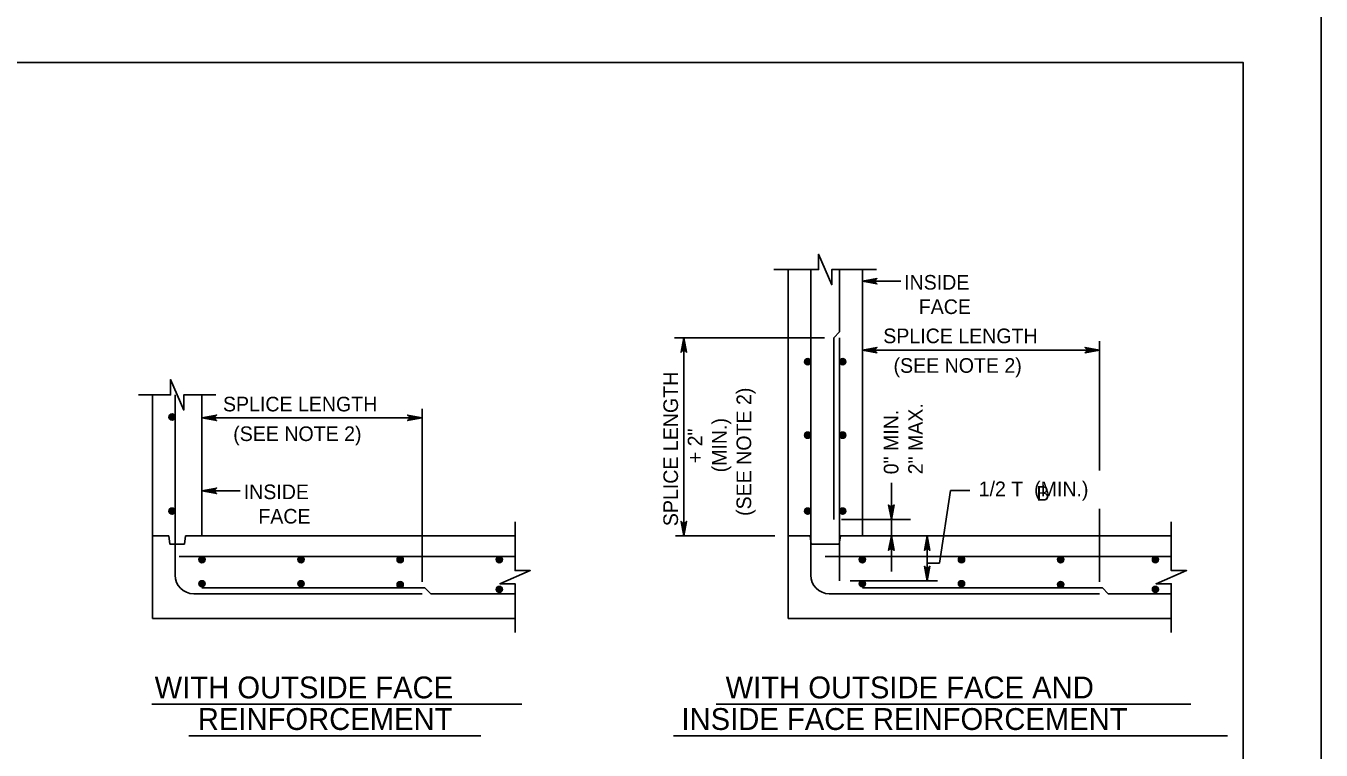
# Model space of a CAD drawing. Extents: x -6420 to 49575, y -4552 to 11624.
# Drawn here: x 3745 to 4616, y 7215 to 7702 of the extents above; entities that cross this region are included whole.
import ezdxf

# ---------------------------------------------------------------- set-up
doc = ezdxf.new("R2010")
doc.units = 0
doc.layers.add('1', color=7, linetype='Continuous')
doc.layers.add('PLT-BNDY', color=7, linetype='Continuous')

msp = doc.modelspace()

# ---------------------------------------------------------------- linework, layer by layer
at = {"layer": '1'}
for p, q in [((4257.79, 7303.09), (4257.79, 7537.79)), ((4273.09, 7332.26), (4273.09, 7537.79)), ((4292.49, 7495.98), (4292.49, 7537.79)), ((4307.79, 7537.79), (4307.79, 7358.65)), ((4307.79, 7529.92), (4333.56, 7529.92)), ((4292.49, 7495.98), (4288.49, 7491.98)), ((4181.37, 7491.98), (4282.24, 7491.98)), ((4187.65, 7491.98), (4187.65, 7358.65)), ((4288.49, 7369.76), (4288.49, 7491.98)), ((4292.49, 7328.51), (4292.49, 7491.98)), ((4467.38, 7489.73), (4467.38, 7402.75)), ((4307.79, 7483.63), (4467.38, 7483.63)), ((3830.2, 7303.09), (3830.2, 7453.51)), ((3845.48, 7332.26), (3845.48, 7453.51)), ((3863.53, 7453.51), (3863.53, 7358.65)), ((4011.69, 7444.18), (4011.69, 7327.74)), ((3863.53, 7438.09), (4011.69, 7438.09)), ((3863.53, 7389), (3889.3, 7389)), ((4327.28, 7334.61), (4327.28, 7394.25)), ((4367.02, 7389.18), (4359.63, 7340.25)), ((4367.02, 7389.18), (4380.11, 7389.18)), ((4467.38, 7376.76), (4467.38, 7327.74)), ((4293.74, 7369.76), (4340.2, 7369.76)), ((3830.18, 7358.65), (3841.31, 7358.65)), ((3842, 7353.1), (3841.31, 7358.65)), ((3851.72, 7353.1), (3852.41, 7358.65)), ((3852.41, 7358.65), (3863.53, 7358.65)), ((3863.53, 7358.65), (4074.18, 7358.65)), ((4181.99, 7358.65), (4248.82, 7358.65)), ((4257.79, 7358.65), (4272.61, 7358.65)), ((4273.3, 7353.1), (4272.61, 7358.65)), ((4292.28, 7353.1), (4292.98, 7358.65)), ((4292.98, 7358.65), (4307.79, 7358.65)), ((4307.79, 7358.65), (4515.61, 7358.65)), ((4351.32, 7358.65), (4351.32, 7328.51)), ((3842, 7353.1), (3851.72, 7353.1)), ((4273.3, 7353.1), (4292.28, 7353.1)), ((3848.25, 7344.76), (4074.18, 7344.76)), ((4282.79, 7344.76), (4515.61, 7344.76)), ((4351.32, 7340.25), (4359.63, 7340.25)), ((4299.51, 7328.51), (4358.23, 7328.51)), ((4011.69, 7319.76), (3857.98, 7319.76)), ((4013.53, 7323.76), (3863.53, 7323.76)), ((4013.53, 7323.76), (4017.53, 7319.76)), ((4074.18, 7319.76), (4017.53, 7319.76)), ((4467.38, 7319.76), (4285.57, 7319.76)), ((4469.22, 7323.76), (4307.79, 7323.76)), ((4469.22, 7323.76), (4473.22, 7319.76)), ((4515.61, 7319.76), (4473.22, 7319.76)), ((4074.18, 7303.09), (3830.2, 7303.09)), ((4515.61, 7303.09), (4257.79, 7303.09)), ((3829.77, 7245.44), (4078.64, 7245.44)), ((4209.48, 7245.44), (4528.86, 7245.44)), ((3854.61, 7224.24), (4051.15, 7224.24)), ((4180.81, 7224.24), (4553.42, 7224.24))]:
    msp.add_line(p, q, dxfattribs=at)
for points in [[(4563.89, 5826.65), (4563.89, 7677.05), (1985.15, 7677.05), (1985.15, 5826.65), (4563.89, 5826.65), (4563.89, 5913.13), (3907.72, 5913.13), (3907.72, 6125.33), (4563.89, 6125.33), (4563.89, 6220.35), (3907.72, 6220.35), (3907.72, 5826.65), (4166.25, 5826.65), (4166.25, 5913.13), (4166.25, 5826.65), (4418.88, 5826.65), (4418.88, 5913.13), (4418.88, 5872.72), (4563.89, 5872.72)], [(4248.34, 7537.79), (4278.38, 7537.79), (4278.38, 7548.03), (4287.2, 7527.56), (4287.2, 7537.79), (4317.24, 7537.79)], [(4307.79, 7529.92), (4317.58, 7531.76), (4317.2, 7531.5), (4316.82, 7531.24), (4316.63, 7530.91), (4316.43, 7530.58), (4316.38, 7530.25), (4316.32, 7529.92), (4316.38, 7529.59), (4316.43, 7529.27), (4316.63, 7528.94), (4316.82, 7528.61), (4317.2, 7528.35), (4317.58, 7528.09), (4307.79, 7529.92), (4317.2, 7528.35), (4316.82, 7528.61), (4307.79, 7529.92), (4316.63, 7528.94), (4316.43, 7529.27), (4307.79, 7529.92), (4316.38, 7529.59), (4316.32, 7529.92), (4307.79, 7529.92), (4316.38, 7530.25), (4316.43, 7530.58), (4307.79, 7529.92), (4316.63, 7530.91), (4316.82, 7531.24), (4307.79, 7529.92), (4317.2, 7531.5)], [(4187.65, 7491.98), (4189.49, 7482.2), (4189.22, 7482.57), (4188.96, 7482.95), (4188.63, 7483.15), (4188.31, 7483.34), (4187.98, 7483.4), (4187.65, 7483.45), (4187.32, 7483.4), (4186.99, 7483.34), (4186.67, 7483.15), (4186.34, 7482.95), (4186.08, 7482.57), (4185.82, 7482.2), (4187.65, 7491.98), (4186.08, 7482.57), (4186.34, 7482.95), (4187.65, 7491.98), (4186.67, 7483.15), (4186.99, 7483.34), (4187.65, 7491.98), (4187.32, 7483.4), (4187.65, 7483.45), (4187.65, 7491.98), (4187.98, 7483.4), (4188.31, 7483.34), (4187.65, 7491.98), (4188.63, 7483.15), (4188.96, 7482.95), (4187.65, 7491.98), (4189.22, 7482.57)], [(4307.79, 7483.63), (4317.58, 7485.46), (4317.2, 7485.2), (4316.82, 7484.94), (4316.63, 7484.61), (4316.43, 7484.29), (4316.38, 7483.96), (4316.32, 7483.63), (4316.38, 7483.3), (4316.43, 7482.97), (4316.63, 7482.64), (4316.82, 7482.32), (4317.2, 7482.06), (4317.58, 7481.79), (4307.79, 7483.63), (4317.2, 7482.06), (4316.82, 7482.32), (4307.79, 7483.63), (4316.63, 7482.64), (4316.43, 7482.97), (4307.79, 7483.63), (4316.38, 7483.3), (4316.32, 7483.63), (4307.79, 7483.63), (4316.38, 7483.96), (4316.43, 7484.29), (4307.79, 7483.63), (4316.63, 7484.61), (4316.82, 7484.94), (4307.79, 7483.63), (4317.2, 7485.2)], [(4467.38, 7483.63), (4457.59, 7481.79), (4457.97, 7482.06), (4458.35, 7482.32), (4458.54, 7482.64), (4458.74, 7482.97), (4458.79, 7483.3), (4458.85, 7483.63), (4458.79, 7483.96), (4458.74, 7484.29), (4458.54, 7484.61), (4458.35, 7484.94), (4457.97, 7485.2), (4457.59, 7485.46), (4467.38, 7483.63), (4457.97, 7485.2), (4458.35, 7484.94), (4467.38, 7483.63), (4458.54, 7484.61), (4458.74, 7484.29), (4467.38, 7483.63), (4458.79, 7483.96), (4458.85, 7483.63), (4467.38, 7483.63), (4458.79, 7483.3), (4458.74, 7482.97), (4467.38, 7483.63), (4458.54, 7482.64), (4458.35, 7482.32), (4467.38, 7483.63), (4457.97, 7482.06)], [(3872.98, 7453.51), (3851.28, 7453.51), (3851.28, 7443.28), (3842.46, 7463.75), (3842.46, 7453.51), (3820.75, 7453.51)], [(3863.53, 7438.09), (3873.32, 7439.93), (3872.94, 7439.67), (3872.57, 7439.41), (3872.37, 7439.08), (3872.18, 7438.75), (3872.12, 7438.42), (3872.06, 7438.09), (3872.12, 7437.77), (3872.18, 7437.44), (3872.37, 7437.11), (3872.57, 7436.78), (3872.94, 7436.52), (3873.32, 7436.26), (3863.53, 7438.09), (3872.94, 7436.52), (3872.57, 7436.78), (3863.53, 7438.09), (3872.37, 7437.11), (3872.18, 7437.44), (3863.53, 7438.09), (3872.12, 7437.77), (3872.06, 7438.09), (3863.53, 7438.09), (3872.12, 7438.42), (3872.18, 7438.75), (3863.53, 7438.09), (3872.37, 7439.08), (3872.57, 7439.41), (3863.53, 7438.09), (3872.94, 7439.67)], [(4011.69, 7438.09), (4001.91, 7436.26), (4002.28, 7436.52), (4002.66, 7436.78), (4002.86, 7437.11), (4003.05, 7437.44), (4003.11, 7437.77), (4003.16, 7438.09), (4003.11, 7438.42), (4003.05, 7438.75), (4002.86, 7439.08), (4002.66, 7439.41), (4002.28, 7439.67), (4001.91, 7439.93), (4011.69, 7438.09), (4002.28, 7439.67), (4002.66, 7439.41), (4011.69, 7438.09), (4002.86, 7439.08), (4003.05, 7438.75), (4011.69, 7438.09), (4003.11, 7438.42), (4003.16, 7438.09), (4011.69, 7438.09), (4003.11, 7437.77), (4003.05, 7437.44), (4011.69, 7438.09), (4002.86, 7437.11), (4002.66, 7436.78), (4011.69, 7438.09), (4002.28, 7436.52)], [(3863.53, 7389), (3873.32, 7390.84), (3872.94, 7390.57), (3872.57, 7390.31), (3872.37, 7389.99), (3872.18, 7389.66), (3872.12, 7389.33), (3872.06, 7389), (3872.12, 7388.67), (3872.18, 7388.34), (3872.37, 7388.02), (3872.57, 7387.69), (3872.94, 7387.43), (3873.32, 7387.17), (3863.53, 7389), (3872.94, 7387.43), (3872.57, 7387.69), (3863.53, 7389), (3872.37, 7388.02), (3872.18, 7388.34), (3863.53, 7389), (3872.12, 7388.67), (3872.06, 7389), (3863.53, 7389), (3872.12, 7389.33), (3872.18, 7389.66), (3863.53, 7389), (3872.37, 7389.99), (3872.57, 7390.31), (3863.53, 7389), (3872.94, 7390.57)], [(4327.28, 7369.76), (4325.44, 7379.55), (4325.71, 7379.17), (4325.97, 7378.79), (4326.29, 7378.6), (4326.62, 7378.41), (4326.95, 7378.35), (4327.28, 7378.29), (4327.61, 7378.35), (4327.94, 7378.41), (4328.26, 7378.6), (4328.59, 7378.79), (4328.85, 7379.17), (4329.11, 7379.55), (4327.28, 7369.76), (4328.85, 7379.17), (4328.59, 7378.79), (4327.28, 7369.76), (4328.26, 7378.6), (4327.94, 7378.41), (4327.28, 7369.76), (4327.61, 7378.35), (4327.28, 7378.29), (4327.28, 7369.76), (4326.95, 7378.35), (4326.62, 7378.41), (4327.28, 7369.76), (4326.29, 7378.6), (4325.97, 7378.79), (4327.28, 7369.76), (4325.71, 7379.17)], [(4074.18, 7368.1), (4074.18, 7335.28), (4084.42, 7335.28), (4063.94, 7326.46), (4074.18, 7326.46), (4074.18, 7293.64)], [(4187.65, 7358.65), (4185.82, 7368.43), (4186.08, 7368.06), (4186.34, 7367.68), (4186.67, 7367.49), (4186.99, 7367.29), (4187.32, 7367.24), (4187.65, 7367.18), (4187.98, 7367.24), (4188.31, 7367.29), (4188.63, 7367.49), (4188.96, 7367.68), (4189.22, 7368.06), (4189.49, 7368.43), (4187.65, 7358.65), (4189.22, 7368.06), (4188.96, 7367.68), (4187.65, 7358.65), (4188.63, 7367.49), (4188.31, 7367.29), (4187.65, 7358.65), (4187.98, 7367.24), (4187.65, 7367.18), (4187.65, 7358.65), (4187.32, 7367.24), (4186.99, 7367.29), (4187.65, 7358.65), (4186.67, 7367.49), (4186.34, 7367.68), (4187.65, 7358.65), (4186.08, 7368.06)], [(4515.61, 7368.1), (4515.61, 7335.28), (4525.85, 7335.28), (4505.37, 7326.46), (4515.61, 7326.46), (4515.61, 7293.64)], [(4327.28, 7358.65), (4329.11, 7348.86), (4328.85, 7349.24), (4328.59, 7349.62), (4328.26, 7349.81), (4327.94, 7350.01), (4327.61, 7350.06), (4327.28, 7350.12), (4326.95, 7350.06), (4326.62, 7350.01), (4326.29, 7349.81), (4325.97, 7349.62), (4325.71, 7349.24), (4325.44, 7348.86), (4327.28, 7358.65), (4325.71, 7349.24), (4325.97, 7349.62), (4327.28, 7358.65), (4326.29, 7349.81), (4326.62, 7350.01), (4327.28, 7358.65), (4326.95, 7350.06), (4327.28, 7350.12), (4327.28, 7358.65), (4327.61, 7350.06), (4327.94, 7350.01), (4327.28, 7358.65), (4328.26, 7349.81), (4328.59, 7349.62), (4327.28, 7358.65), (4328.85, 7349.24)], [(4351.32, 7358.65), (4353.16, 7348.86), (4352.9, 7349.24), (4352.64, 7349.62), (4352.31, 7349.81), (4351.98, 7350.01), (4351.65, 7350.06), (4351.32, 7350.12), (4350.99, 7350.06), (4350.67, 7350.01), (4350.34, 7349.81), (4350.01, 7349.62), (4349.75, 7349.24), (4349.49, 7348.86), (4351.32, 7358.65), (4349.75, 7349.24), (4350.01, 7349.62), (4351.32, 7358.65), (4350.34, 7349.81), (4350.67, 7350.01), (4351.32, 7358.65), (4350.99, 7350.06), (4351.32, 7350.12), (4351.32, 7358.65), (4351.65, 7350.06), (4351.98, 7350.01), (4351.32, 7358.65), (4352.31, 7349.81), (4352.64, 7349.62), (4351.32, 7358.65), (4352.9, 7349.24)], [(4351.32, 7328.51), (4349.49, 7338.29), (4349.75, 7337.92), (4350.01, 7337.54), (4350.34, 7337.34), (4350.67, 7337.15), (4350.99, 7337.09), (4351.32, 7337.04), (4351.65, 7337.09), (4351.98, 7337.15), (4352.31, 7337.34), (4352.64, 7337.54), (4352.9, 7337.92), (4353.16, 7338.29), (4351.32, 7328.51), (4352.9, 7337.92), (4352.64, 7337.54), (4351.32, 7328.51), (4352.31, 7337.34), (4351.98, 7337.15), (4351.32, 7328.51), (4351.65, 7337.09), (4351.32, 7337.04), (4351.32, 7328.51), (4350.99, 7337.09), (4350.67, 7337.15), (4351.32, 7328.51), (4350.34, 7337.34), (4350.01, 7337.54), (4351.32, 7328.51), (4349.75, 7337.92)]]:
    msp.add_lwpolyline(points, dxfattribs=at)
for centre, radius in [((4271, 7475.83), 2.08), ((4271, 7475.83), 1.94), ((4271, 7475.83), 1.79), ((4271, 7475.83), 1.64), ((4271, 7475.83), 1.49), ((4271, 7475.83), 1.34), ((4271, 7475.83), 1.2), ((4271, 7475.83), 1.05), ((4271, 7475.83), 0.9), ((4271, 7475.83), 0.752), ((4271, 7475.83), 0.604), ((4271, 7475.83), 0.456), ((4271, 7475.83), 0.308), ((4271, 7475.83), 0.16), ((4294.58, 7475.83), 2.08), ((4294.58, 7475.83), 1.94), ((4294.58, 7475.83), 1.79), ((4294.58, 7475.83), 1.64), ((4294.58, 7475.83), 1.49), ((4294.58, 7475.83), 1.34), ((4294.58, 7475.83), 1.2), ((4294.58, 7475.83), 1.05), ((4294.58, 7475.83), 0.9), ((4294.58, 7475.83), 0.752), ((4294.58, 7475.83), 0.604), ((4294.58, 7475.83), 0.456), ((4294.58, 7475.83), 0.308), ((4294.58, 7475.83), 0.16), ((3843.4, 7438.61), 2.08), ((3843.4, 7438.61), 1.94), ((3843.4, 7438.61), 1.79), ((3843.4, 7438.61), 1.64), ((3843.4, 7438.61), 1.49), ((3843.4, 7438.61), 1.34), ((3843.4, 7438.61), 1.2), ((3843.4, 7438.61), 1.05), ((3843.4, 7438.61), 0.9), ((3843.4, 7438.61), 0.752), ((3843.4, 7438.61), 0.604), ((3843.4, 7438.61), 0.456), ((3843.4, 7438.61), 0.308), ((3843.4, 7438.61), 0.16), ((4271, 7426.41), 2.08), ((4271, 7426.41), 1.94), ((4271, 7426.41), 1.79), ((4271, 7426.41), 1.64), ((4271, 7426.41), 1.49), ((4271, 7426.41), 1.34), ((4271, 7426.41), 1.2), ((4271, 7426.41), 1.05), ((4271, 7426.41), 0.9), ((4271, 7426.41), 0.752), ((4271, 7426.41), 0.604), ((4271, 7426.41), 0.456), ((4271, 7426.41), 0.308), ((4271, 7426.41), 0.16), ((4294.58, 7426.41), 2.08), ((4294.58, 7426.41), 1.94), ((4294.58, 7426.41), 1.79), ((4294.58, 7426.41), 1.64), ((4294.58, 7426.41), 1.49), ((4294.58, 7426.41), 1.34), ((4294.58, 7426.41), 1.2), ((4294.58, 7426.41), 1.05), ((4294.58, 7426.41), 0.9), ((4294.58, 7426.41), 0.752), ((4294.58, 7426.41), 0.604), ((4294.58, 7426.41), 0.456), ((4294.58, 7426.41), 0.308), ((4294.58, 7426.41), 0.16), ((3843.4, 7375.32), 2.08), ((3843.4, 7375.32), 1.94), ((3843.4, 7375.32), 1.79), ((3843.4, 7375.32), 1.64), ((3843.4, 7375.32), 1.49), ((3843.4, 7375.32), 1.34), ((3843.4, 7375.32), 1.2), ((3843.4, 7375.32), 1.05), ((3843.4, 7375.32), 0.9), ((3843.4, 7375.32), 0.752), ((3843.4, 7375.32), 0.604), ((3843.4, 7375.32), 0.456), ((3843.4, 7375.32), 0.308), ((3843.4, 7375.32), 0.16), ((4271, 7375.32), 2.08), ((4271, 7375.32), 1.94), ((4271, 7375.32), 1.79), ((4271, 7375.32), 1.64), ((4271, 7375.32), 1.49), ((4271, 7375.32), 1.34), ((4271, 7375.32), 1.2), ((4271, 7375.32), 1.05), ((4271, 7375.32), 0.9), ((4271, 7375.32), 0.752), ((4271, 7375.32), 0.604), ((4271, 7375.32), 0.456), ((4271, 7375.32), 0.308), ((4271, 7375.32), 0.16), ((4294.58, 7375.32), 2.08), ((4294.58, 7375.32), 1.94), ((4294.58, 7375.32), 1.79), ((4294.58, 7375.32), 1.64), ((4294.58, 7375.32), 1.49), ((4294.58, 7375.32), 1.34), ((4294.58, 7375.32), 1.2), ((4294.58, 7375.32), 1.05), ((4294.58, 7375.32), 0.9), ((4294.58, 7375.32), 0.752), ((4294.58, 7375.32), 0.604), ((4294.58, 7375.32), 0.456), ((4294.58, 7375.32), 0.308), ((4294.58, 7375.32), 0.16), ((3863.53, 7342.68), 2.08), ((3863.53, 7342.68), 1.94), ((3863.53, 7342.68), 1.79), ((3863.53, 7342.68), 1.64), ((3863.53, 7342.68), 1.49), ((3863.53, 7342.68), 1.34), ((3863.53, 7342.68), 1.2), ((3863.53, 7342.68), 1.05), ((3863.53, 7342.68), 0.9), ((3863.53, 7342.68), 0.752), ((3863.53, 7342.68), 0.604), ((3863.53, 7342.68), 0.456), ((3863.53, 7342.68), 0.308), ((3863.53, 7342.68), 0.16), ((3930.2, 7342.68), 2.08), ((3930.2, 7342.68), 1.94), ((3930.2, 7342.68), 1.79), ((3930.2, 7342.68), 1.64), ((3930.2, 7342.68), 1.49), ((3930.2, 7342.68), 1.34), ((3930.2, 7342.68), 1.2), ((3930.2, 7342.68), 1.05), ((3930.2, 7342.68), 0.9), ((3930.2, 7342.68), 0.752), ((3930.2, 7342.68), 0.604), ((3930.2, 7342.68), 0.456), ((3930.2, 7342.68), 0.308), ((3930.2, 7342.68), 0.16), ((3996.87, 7342.68), 2.08), ((3996.87, 7342.68), 1.94), ((3996.87, 7342.68), 1.79), ((3996.87, 7342.68), 1.64), ((3996.87, 7342.68), 1.49), ((3996.87, 7342.68), 1.34), ((3996.87, 7342.68), 1.2), ((3996.87, 7342.68), 1.05), ((3996.87, 7342.68), 0.9), ((3996.87, 7342.68), 0.752), ((3996.87, 7342.68), 0.604), ((3996.87, 7342.68), 0.456), ((3996.87, 7342.68), 0.308), ((3996.87, 7342.68), 0.16), ((4063.53, 7342.68), 2.08), ((4063.53, 7342.68), 1.94), ((4063.53, 7342.68), 1.79), ((4063.53, 7342.68), 1.64), ((4063.53, 7342.68), 1.49), ((4063.53, 7342.68), 1.34), ((4063.53, 7342.68), 1.2), ((4063.53, 7342.68), 1.05), ((4063.53, 7342.68), 0.9), ((4063.53, 7342.68), 0.752), ((4063.53, 7342.68), 0.604), ((4063.53, 7342.68), 0.456), ((4063.53, 7342.68), 0.308), ((4063.53, 7342.68), 0.16), ((4307.8, 7342.68), 2.08), ((4307.8, 7342.68), 1.94), ((4307.8, 7342.68), 1.79), ((4307.8, 7342.68), 1.64), ((4307.8, 7342.68), 1.49), ((4307.8, 7342.68), 1.34), ((4307.8, 7342.68), 1.2), ((4307.8, 7342.68), 1.05), ((4307.8, 7342.68), 0.9), ((4307.8, 7342.68), 0.752), ((4307.8, 7342.68), 0.604), ((4307.8, 7342.68), 0.456), ((4307.8, 7342.68), 0.308), ((4307.8, 7342.68), 0.16), ((4374.47, 7342.68), 2.08), ((4374.47, 7342.68), 1.94), ((4374.47, 7342.68), 1.79), ((4374.47, 7342.68), 1.64), ((4374.47, 7342.68), 1.49), ((4374.47, 7342.68), 1.34), ((4374.47, 7342.68), 1.2), ((4374.47, 7342.68), 1.05), ((4374.47, 7342.68), 0.9), ((4374.47, 7342.68), 0.752), ((4374.47, 7342.68), 0.604), ((4374.47, 7342.68), 0.456), ((4374.47, 7342.68), 0.308), ((4374.47, 7342.68), 0.16), ((4441.13, 7342.68), 2.08), ((4441.13, 7342.68), 1.94), ((4441.13, 7342.68), 1.79), ((4441.13, 7342.68), 1.64), ((4441.13, 7342.68), 1.49), ((4441.13, 7342.68), 1.34), ((4441.13, 7342.68), 1.2), ((4441.13, 7342.68), 1.05), ((4441.13, 7342.68), 0.9), ((4441.13, 7342.68), 0.752), ((4441.13, 7342.68), 0.604), ((4441.13, 7342.68), 0.456), ((4441.13, 7342.68), 0.308), ((4441.13, 7342.68), 0.16), ((4504.96, 7342.68), 2.08), ((4504.96, 7342.68), 1.94), ((4504.96, 7342.68), 1.79), ((4504.96, 7342.68), 1.64), ((4504.96, 7342.68), 1.49), ((4504.96, 7342.68), 1.34), ((4504.96, 7342.68), 1.2), ((4504.96, 7342.68), 1.05), ((4504.96, 7342.68), 0.9), ((4504.96, 7342.68), 0.752), ((4504.96, 7342.68), 0.604), ((4504.96, 7342.68), 0.456), ((4504.96, 7342.68), 0.308), ((4504.96, 7342.68), 0.16), ((3863.53, 7326.44), 2.08), ((3863.53, 7326.44), 1.94), ((3863.53, 7326.44), 1.79), ((3863.53, 7326.44), 1.64), ((3863.53, 7326.44), 1.49), ((3863.53, 7326.44), 1.34), ((3863.53, 7326.44), 1.2), ((3863.53, 7326.44), 1.05), ((3930.2, 7326.44), 2.08), ((3930.2, 7326.44), 1.94), ((3930.2, 7326.44), 1.79), ((3930.2, 7326.44), 1.64), ((3930.2, 7326.44), 1.49), ((3930.2, 7326.44), 1.34), ((3930.2, 7326.44), 1.2), ((3930.2, 7326.44), 1.05), ((3996.87, 7325.88), 2.08), ((3996.87, 7325.88), 1.94), ((3996.87, 7325.88), 1.79), ((3996.87, 7325.88), 1.64), ((4307.8, 7326.44), 2.08), ((4307.8, 7326.44), 1.94), ((4307.8, 7326.44), 1.79), ((4307.8, 7326.44), 1.64), ((4307.8, 7326.44), 1.49), ((4307.8, 7326.44), 1.34), ((4307.8, 7326.44), 1.2), ((4307.8, 7326.44), 1.05), ((4374.47, 7326.44), 2.08), ((4374.47, 7326.44), 1.94), ((4374.47, 7326.44), 1.79), ((4374.47, 7326.44), 1.64), ((4374.47, 7326.44), 1.49), ((4374.47, 7326.44), 1.34), ((4374.47, 7326.44), 1.2), ((4374.47, 7326.44), 1.05), ((4441.13, 7325.88), 2.08), ((4441.13, 7325.88), 1.94), ((4441.13, 7325.88), 1.79), ((4441.13, 7325.88), 1.64), ((3863.53, 7326.44), 0.9), ((3863.53, 7326.44), 0.752), ((3863.53, 7326.44), 0.604), ((3863.53, 7326.44), 0.456), ((3863.53, 7326.44), 0.308), ((3863.53, 7326.44), 0.16), ((3930.2, 7326.44), 0.9), ((3930.2, 7326.44), 0.752), ((3930.2, 7326.44), 0.604), ((3930.2, 7326.44), 0.456), ((3930.2, 7326.44), 0.308), ((3930.2, 7326.44), 0.16), ((3996.87, 7325.88), 1.49), ((3996.87, 7325.88), 1.34), ((3996.87, 7325.88), 1.2), ((3996.87, 7325.88), 1.05), ((3996.87, 7325.88), 0.9), ((3996.87, 7325.88), 0.752), ((3996.87, 7325.88), 0.604), ((3996.87, 7325.88), 0.456), ((3996.87, 7325.88), 0.308), ((3996.87, 7325.88), 0.16), ((4063.53, 7322.63), 2.08), ((4063.53, 7322.63), 1.94), ((4063.53, 7322.63), 1.79), ((4063.53, 7322.63), 1.64), ((4063.53, 7322.63), 1.49), ((4063.53, 7322.63), 1.34), ((4063.53, 7322.63), 1.2), ((4063.53, 7322.63), 1.05), ((4063.53, 7322.63), 0.9), ((4063.53, 7322.63), 0.752), ((4063.53, 7322.63), 0.604), ((4063.53, 7322.63), 0.456), ((4063.53, 7322.63), 0.308), ((4063.53, 7322.63), 0.16), ((4307.8, 7326.44), 0.9), ((4307.8, 7326.44), 0.752), ((4307.8, 7326.44), 0.604), ((4307.8, 7326.44), 0.456), ((4307.8, 7326.44), 0.308), ((4307.8, 7326.44), 0.16), ((4374.47, 7326.44), 0.9), ((4374.47, 7326.44), 0.752), ((4374.47, 7326.44), 0.604), ((4374.47, 7326.44), 0.456), ((4374.47, 7326.44), 0.308), ((4374.47, 7326.44), 0.16), ((4441.13, 7325.88), 1.49), ((4441.13, 7325.88), 1.34), ((4441.13, 7325.88), 1.2), ((4441.13, 7325.88), 1.05), ((4441.13, 7325.88), 0.9), ((4441.13, 7325.88), 0.752), ((4441.13, 7325.88), 0.604), ((4441.13, 7325.88), 0.456), ((4441.13, 7325.88), 0.308), ((4441.13, 7325.88), 0.16), ((4504.96, 7322.63), 2.08), ((4504.96, 7322.63), 1.94), ((4504.96, 7322.63), 1.79), ((4504.96, 7322.63), 1.64), ((4504.96, 7322.63), 1.49), ((4504.96, 7322.63), 1.34), ((4504.96, 7322.63), 1.2), ((4504.96, 7322.63), 1.05), ((4504.96, 7322.63), 0.9), ((4504.96, 7322.63), 0.752), ((4504.96, 7322.63), 0.604), ((4504.96, 7322.63), 0.456), ((4504.96, 7322.63), 0.308), ((4504.96, 7322.63), 0.16)]:
    msp.add_circle(centre, radius, dxfattribs=at)
for centre in [(3857.98, 7332.26), (4285.59, 7332.26)]:
    msp.add_arc(centre, 12.5, 180, 270, dxfattribs=at)
at = {"layer": 'PLT-BNDY'}
msp.add_lwpolyline([(1857.19, 7726.26), (4616.38, 7726.26), (4616.38, 5777.44), (1857.19, 5777.44)], close=True, dxfattribs=at)

# ---------------------------------------------------------------- texts
at = {"layer": '1'}
for s, height, p in [('INSIDE', 9.843, (4335.89, 7524.29)), ('FACE', 9.843, (4345.73, 7507.89)), ('SPLICE LENGTH', 9.8425, (4321.85, 7488.26)), ('(SEE NOTE 2)', 9.8425, (4328.75, 7468.34)), ('SPLICE LENGTH', 9.8425, (3877.67, 7442.39)), ('(SEE NOTE 2)', 9.8425, (3884.57, 7422.46)), ('INSIDE', 9.843, (3891.63, 7383.37)), ('1/2 T  (MIN.)', 9.8425, (4386.02, 7385.37)), ('B', 9.84, (4424.87, 7382.34)), ('FACE', 9.843, (3901.47, 7366.96)), ('WITH OUTSIDE FACE', 14.6898, (3831.7, 7249.4)), ('WITH OUTSIDE FACE AND', 14.6898, (4215.77, 7249.4)), ('REINFORCEMENT', 14.6898, (3860.73, 7228.15)), ('INSIDE FACE REINFORCEMENT', 14.6898, (4186.1, 7228.15))]:
    msp.add_text(s, height=height, dxfattribs=at).set_placement(p)
for s, height, p in [('SPLICE LENGTH', 9.8425, (4183.77, 7365.21)), ('(SEE NOTE 2)', 9.8425, (4232.99, 7372.1)), ('0" MIN.', 9.843, (4332.05, 7400.09)), ('2" MAX.', 9.843, (4348.45, 7400.09)), ('(MIN.)', 9.843, (4216.58, 7401.4)), ('+ 2"', 9.843, (4200.18, 7407.52))]:
    msp.add_text(s, height=height, rotation=90, dxfattribs=at).set_placement(p)

doc.saveas('drawing.dxf')
